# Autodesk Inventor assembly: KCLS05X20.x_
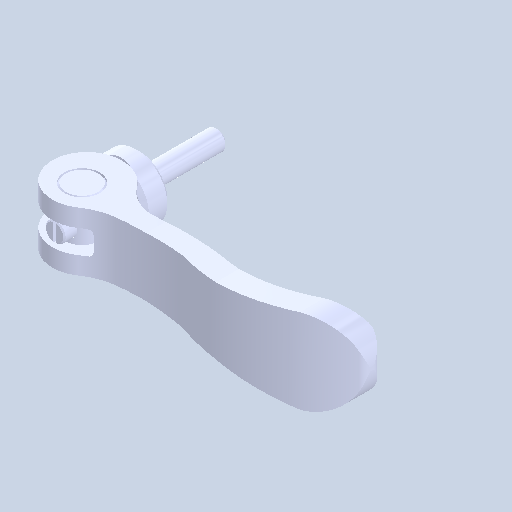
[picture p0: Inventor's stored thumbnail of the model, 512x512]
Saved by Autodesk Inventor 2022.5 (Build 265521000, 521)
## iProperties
Created: 2024-08
Part Number: KCLS05X20.x_
Document SubType Name: Assembly
Designer: ImaoCorp
Author: ImaoCorp
Sending System: SOLIDWORKS 2022-2022290
MC: AMD64
MC_MODEL: Intel64 Family 6 Model 60 Stepping 3, GenuineIntel
OS: Windows_NT
FRU: Parasolid Version 33.1, build 260,  4-25-2022
FORMAT: text
GUISE: transmit
KEY: FILEKCLS05X20.x_t
DATE: Thu Aug 29 10:54:38 2024
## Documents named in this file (5)
- Y:\5.更新分\2024年対応\1001_KCL\データ\kcls05x20\KCLS05X20.x_.iam
- Y:\5.更新分\2024年対応\1001_KCL\データ\kcls05x20\KCLS05X20_01.ipt
- Y:\5.更新分\2024年対応\1001_KCL\データ\kcls05x20\KCLS05X20_02.ipt
- Y:\5.更新分\2024年対応\1001_KCL\データ\kcls05x20\KCLS05X20_03.ipt
- Y:\5.更新分\2024年対応\1001_KCL\データ\kcls05x20\KCLS05X20_04.ipt
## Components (4 placed, 4 different names)
1. KCLS05X20_01
2. KCLS05X20_02
3. KCLS05X20_03
4. KCLS05X20_04
